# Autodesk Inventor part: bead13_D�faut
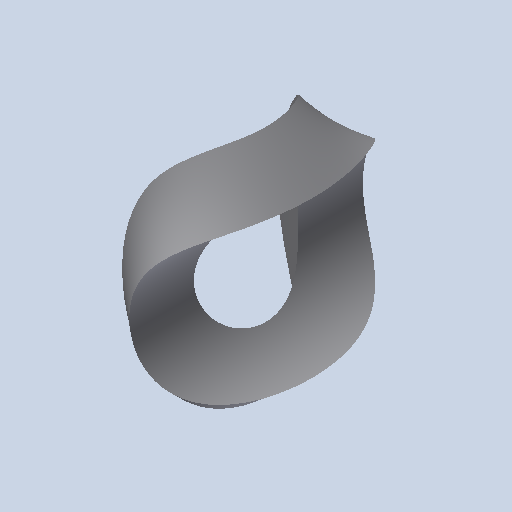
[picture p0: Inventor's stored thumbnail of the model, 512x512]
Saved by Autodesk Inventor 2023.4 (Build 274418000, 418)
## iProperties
Created: 2011-01
Part Number: bead13_D�faut
Document SubType Name: Modeling
Designer: eric
Density: 1 g/cm^3
Mass: 0.113114 g
Surface Area: 2.8981 cm^2
Volume: 0.113114 cm^3
Material: Générique
Appearance: Par défaut
Author: eric
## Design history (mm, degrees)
feature "Base1"
node "Corps solides"
node "Corps surfaciques"
node "Solide1"
